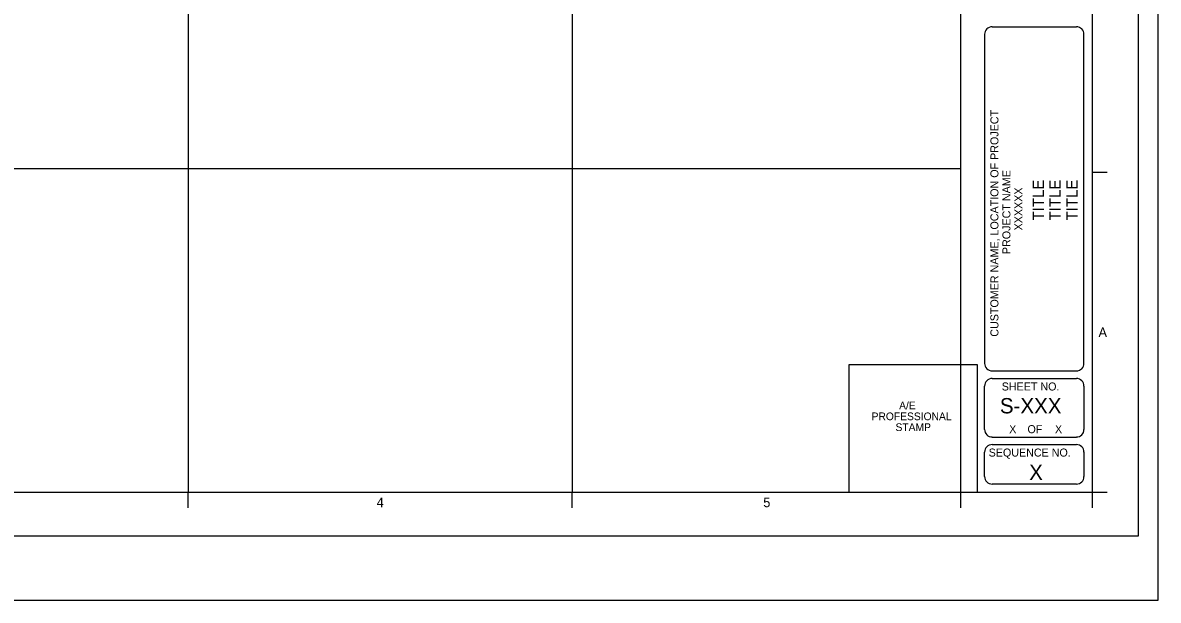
# Model space of a CAD drawing. Extents: x -0.19 to 2.81, y 0.03 to 2.03.
# Drawn here: x 1.329 to 2.806, y 0.032 to 0.783 of the extents above; entities that cross this region are included whole.
import ezdxf

# ---------------------------------------------------------------- set-up
doc = ezdxf.new("R2010")
doc.units = 0
for name, color, linetype in [('G-ANNO-NPLT', 7, 'Continuous'), ('G-ANNO-TEXT', 7, 'Continuous'), ('G-ANNO-TTBL', 7, 'Continuous'), ('S-ANNO-TEXT', 7, 'Continuous')]:
    doc.layers.add(name, color=color, linetype=linetype)

msp = doc.modelspace()

# ---------------------------------------------------------------- linework, layer by layer
at = {"layer": 'G-ANNO-NPLT'}
for p, q in [((2.5495, 0.1551), (2.5495, 1.9077)), ((1.5442, 1.8993), (1.5442, 0.1724)), ((2.0436, 1.8993), (2.0436, 0.1724)), ((2.5495, 0.5933), (0.0565, 0.5933))]:
    msp.add_line(p, q, dxfattribs=at)
at = {"layer": 'G-ANNO-TTBL'}
for p, q in [((2.7202, 1.919), (2.7202, 0.1527)), ((2.7202, 0.5891), (2.7398, 0.5891)), ((2.7398, 0.1724), (0.0368, 0.1724)), ((1.5442, 0.1527), (1.5442, 0.1724)), ((2.0436, 0.1527), (2.0436, 0.1724)), ((2.5495, 0.1527), (2.5495, 0.1724))]:
    msp.add_line(p, q, dxfattribs=at)
for points in [[(2.8064, 2.0324), (-0.1936, 2.0324), (-0.1936, 0.0324), (2.8064, 0.0324)], [(-0.053, 1.9491), (2.7804, 1.9491), (2.7804, 0.1157), (-0.053, 0.1157)], [(2.4041, 0.3391), (2.5708, 0.3391), (2.5708, 0.1724), (2.4041, 0.1724)]]:
    msp.add_lwpolyline(points, close=True, dxfattribs=at)
for points in [[(2.5903, 0.778), (2.6999, 0.778)], [(2.5804, 0.7681), (2.5804, 0.3404)], [(2.7097, 0.3408), (2.7097, 0.7681)], [(2.5896, 0.3306), (2.6999, 0.3306)], [(2.5804, 0.2545), (2.5804, 0.3109)], [(2.5903, 0.3207), (2.6999, 0.3207)], [(2.7097, 0.3109), (2.7097, 0.2545)], [(2.5903, 0.2446), (2.6999, 0.2446)], [(2.5804, 0.1933), (2.5804, 0.2249)], [(2.5903, 0.2348), (2.6999, 0.2348)], [(2.7097, 0.2255), (2.7097, 0.1933)], [(2.6999, 0.1835), (2.5903, 0.1835)]]:
    msp.add_lwpolyline(points, dxfattribs=at)
for centre, start, end in [((2.5903, 0.7681), 90, 180), ((2.6999, 0.7681), 0, 90), ((2.5903, 0.3404), 180, 270), ((2.6999, 0.3404), 270, 0), ((2.5903, 0.3109), 90, 180), ((2.6999, 0.3109), 0, 90), ((2.5903, 0.2545), 180, 270), ((2.6999, 0.2545), 270, 0), ((2.5903, 0.2249), 90, 180), ((2.6999, 0.2249), 0, 90), ((2.5903, 0.1933), 180, 270), ((2.6999, 0.1933), 270, 0)]:
    msp.add_arc(centre, 0.00984, start, end, dxfattribs=at)
at = {"layer": 'S-ANNO-TEXT'}
msp.add_circle((2.7804, 0.1157), 0.0000168, dxfattribs=at)

# ---------------------------------------------------------------- texts
at = {"layer": 'G-ANNO-TEXT'}
for s, height, p in [('CUSTOMER NAME, LOCATION OF PROJECT', 0.010417, (2.5984, 0.375)), ('PROJECT NAME', 0.010417, (2.614, 0.4824)), ('XXXXXX', 0.01042, (2.6296, 0.5132))]:
    msp.add_text(s, height=height, rotation=90, dxfattribs=at).set_placement(p)
for s, height, p in [('A', 0.0125, (2.7286, 0.3745)), ('SHEET NO.', 0.01042, (2.6027, 0.3051)), ('A/E ', 0.01, (2.4692, 0.2806)), ('PROFESSIONAL', 0.01, (2.4334, 0.2665)), ('STAMP', 0.01, (2.4645, 0.2524)), ('OF', 0.01042, (2.6362, 0.2496)), ('SEQUENCE NO.', 0.010417, (2.5857, 0.2192)), ('4', 0.0125, (1.7894, 0.1534)), ('5', 0.0125, (2.2924, 0.1534))]:
    msp.add_text(s, height=height, dxfattribs=at).set_placement(p)
at = {"layer": 'S-ANNO-TEXT'}
for p in [(2.6575, 0.5261), (2.6794, 0.5261), (2.7013, 0.5261)]:
    msp.add_text('TITLE', height=0.01458, rotation=90, dxfattribs=at).set_placement(p)
for s, height, p in [('S-XXX', 0.01997, (2.6003, 0.2753)), ('X', 0.0104, (2.6124, 0.2496)), ('X', 0.0104, (2.672, 0.2496)), ('X', 0.02, (2.6384, 0.1887))]:
    msp.add_text(s, height=height, dxfattribs=at).set_placement(p)

doc.saveas('drawing.dxf')
